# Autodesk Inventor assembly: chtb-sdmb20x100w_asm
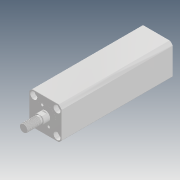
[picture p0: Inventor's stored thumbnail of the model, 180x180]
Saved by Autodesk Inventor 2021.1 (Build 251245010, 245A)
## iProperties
Company: Microsoft
Created: 2018-05
Part Number: chtb-sdmb20x100w_asm
Description: STEP AP214
Document SubType Name: Assembly
Designer: user
Title: chtb-sdmb20x100w_asm.STEP
Author: Windows
Revision Number: ÈÎºÎ
Sending System: SolidWorks 2015
Preprocessor: SwSTEP 2.0
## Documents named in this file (4)
- D:\Vault_2016\Projekty\Clamptek\Hydraulic\CHTB\CHTB-20\Inventor\CHTB-SDMB20x100W\chtb-sdmb20x100w_asm.iam
- D:\Vault_2016\Projekty\Clamptek\Hydraulic\CHTB\CHTB-20\Inventor\CHTB-SDMB20x100W\CHTB-SDMB20X100NBT.ipt
- D:\Vault_2016\Projekty\Clamptek\Hydraulic\CHTB\CHTB-20\Inventor\CHTB-SDMB20x100W\CHTB-SDMB20X100WHSG.ipt
- D:\Vault_2016\Projekty\Clamptek\Hydraulic\CHTB\CHTB-20\Inventor\CHTB-SDMB20x100W\QG_3.ipt
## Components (3 placed, 3 different names)
1. CHTB-SDMB20X100NBT_1
2. CHTB-SDMB20X100WHSG_2
3. QG_3_3
